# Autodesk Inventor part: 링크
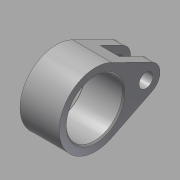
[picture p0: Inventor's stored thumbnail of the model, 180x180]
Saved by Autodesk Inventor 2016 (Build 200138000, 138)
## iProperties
Created: 2016-02
Part Number: 링크
Material: 강철, 연강
Document SubType Name: Modeling
Designer: test
Density: 1 g/cm^3
Appearance: 강철
Author: test
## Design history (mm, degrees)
sketch "스케치1"
  geometry: L1 (20.222, 4.479)-(5.778, 11.645); L2 (20.222, -4.479)-(5.778, -11.645); A1 r 13 centre (0, 0) between (5.778, 11.645) and (5.778, -11.645); A2 r 5 centre (18, 0) between (20.222, -4.479) and (20.222, 4.479); 1 further point
  constraints: 4 end point, 4 point on circle, 4 tangent, 2 centre point, 1 coincident, 1 horizontal alignment
  dimensions: "d0" = 18 distance of point (0, 0) A2.centre; "d1" = 13 radius of A1; "d2" = 5 radius of A2
extrude "돌출1" new body sketch "스케치1" stored distance "d3" = 14; taper "d4" = 0 deg
sketch "스케치2"
  geometry: C1 r 10 at (0, 0); 1 further point
  constraints: 1 centre point, 1 coincident
  dimensions: "d5" = 20 diameter of C1
extrude "돌출2" cut sketch "스케치2" stored distance "d6" = 14; taper "d7" = 0 deg
sketch "스케치3"
  geometry: C1 r 2.5 at (18, 0); A1 r 5 centre (18, 0) between (20.222, -4.479) and (20.222, 4.479) reference; 1 further point
  constraints: 1 centre point, 1 coincident
  dimensions: "d8" = 5 diameter of C1
extrude "돌출3" cut sketch "스케치3" stored distance "d9" = 14; taper "d10" = 0 deg
sketch "스케치4"
  geometry: L1 (20.222, -4.479)-(5.778, -11.645) reference; L2 (5.778, 11.645)-(20.222, 4.479) reference; L3 (12, 8.558)-(12, -8.558); C1 r 2.5 at (18, 0) reference; C2 r 10 at (0, 0) reference; A1 r 13 centre (0, 0) between (5.778, 11.645) and (5.778, -11.645) reference; A2 r 5 centre (18, 0) between (20.222, -4.479) and (20.222, 4.479) reference; 1 further point
  constraints: 2 end point, 2 point on line, 1 vertical
  dimensions: "d11" = 12 distance from line of L3 point (0, 0)
extrude "돌출4" cut sketch "스케치4" stored distance "d12" = 7; taper "d13" = 0 deg
chamfer "모따기1" distance "d14" = 0.5; stored, may be unused: second distance "d15" = 2, angle "d16" = 45 deg
node "솔리드1"
node "절단 모서리 투영1"
